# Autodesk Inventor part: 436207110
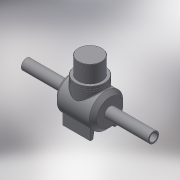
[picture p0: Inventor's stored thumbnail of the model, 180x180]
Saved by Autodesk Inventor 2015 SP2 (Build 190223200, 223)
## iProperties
Created: 2017-08
Part Number: 436207110
Material: Generic
Description: PLASSON PE BALL VALVE 110
Document SubType Name: Modeling
Designer: Кирилл
Density: 1 g/cm^3
Appearance: Default
Author: Кирилл
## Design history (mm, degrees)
derived "436207.ipt"
feature "Solid1::436207.ipt"
feature "Solid2::436207.ipt"
tag "TaggingFeature1"
body "Solid1"
other parameters: "d3" = 178, "d5" = 82.5, "d6" = 16.5, "d10" = 85, "d11" = 68, "d12" = 0.85, "d13" = 4, "d14" = 4, "d16" = 100 deg, "d18" = 16, "d20" = 93, "d21" = 0, "d22" = 0.85, "d28" = 0, "d29" = 1.7, "L_1" = 178, "B_" = 93, "E_1" = 85
